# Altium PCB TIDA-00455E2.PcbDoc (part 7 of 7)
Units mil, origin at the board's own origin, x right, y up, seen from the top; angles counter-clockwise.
Board outline 6693 x 6693.1 mil, 8 copper layers (Layer 1 - Top Layer, Layer 2 - GND, Layer 3 - Sensitive, Layer 4 - GND, Layer 5 - PWR, Layer 6 - Signal, Layer 7 - GND, Layer 8 - Bottom Layer), stack 63.122 mil thick; 537 components, 407 nets, 1686 pads, 1249 vias.
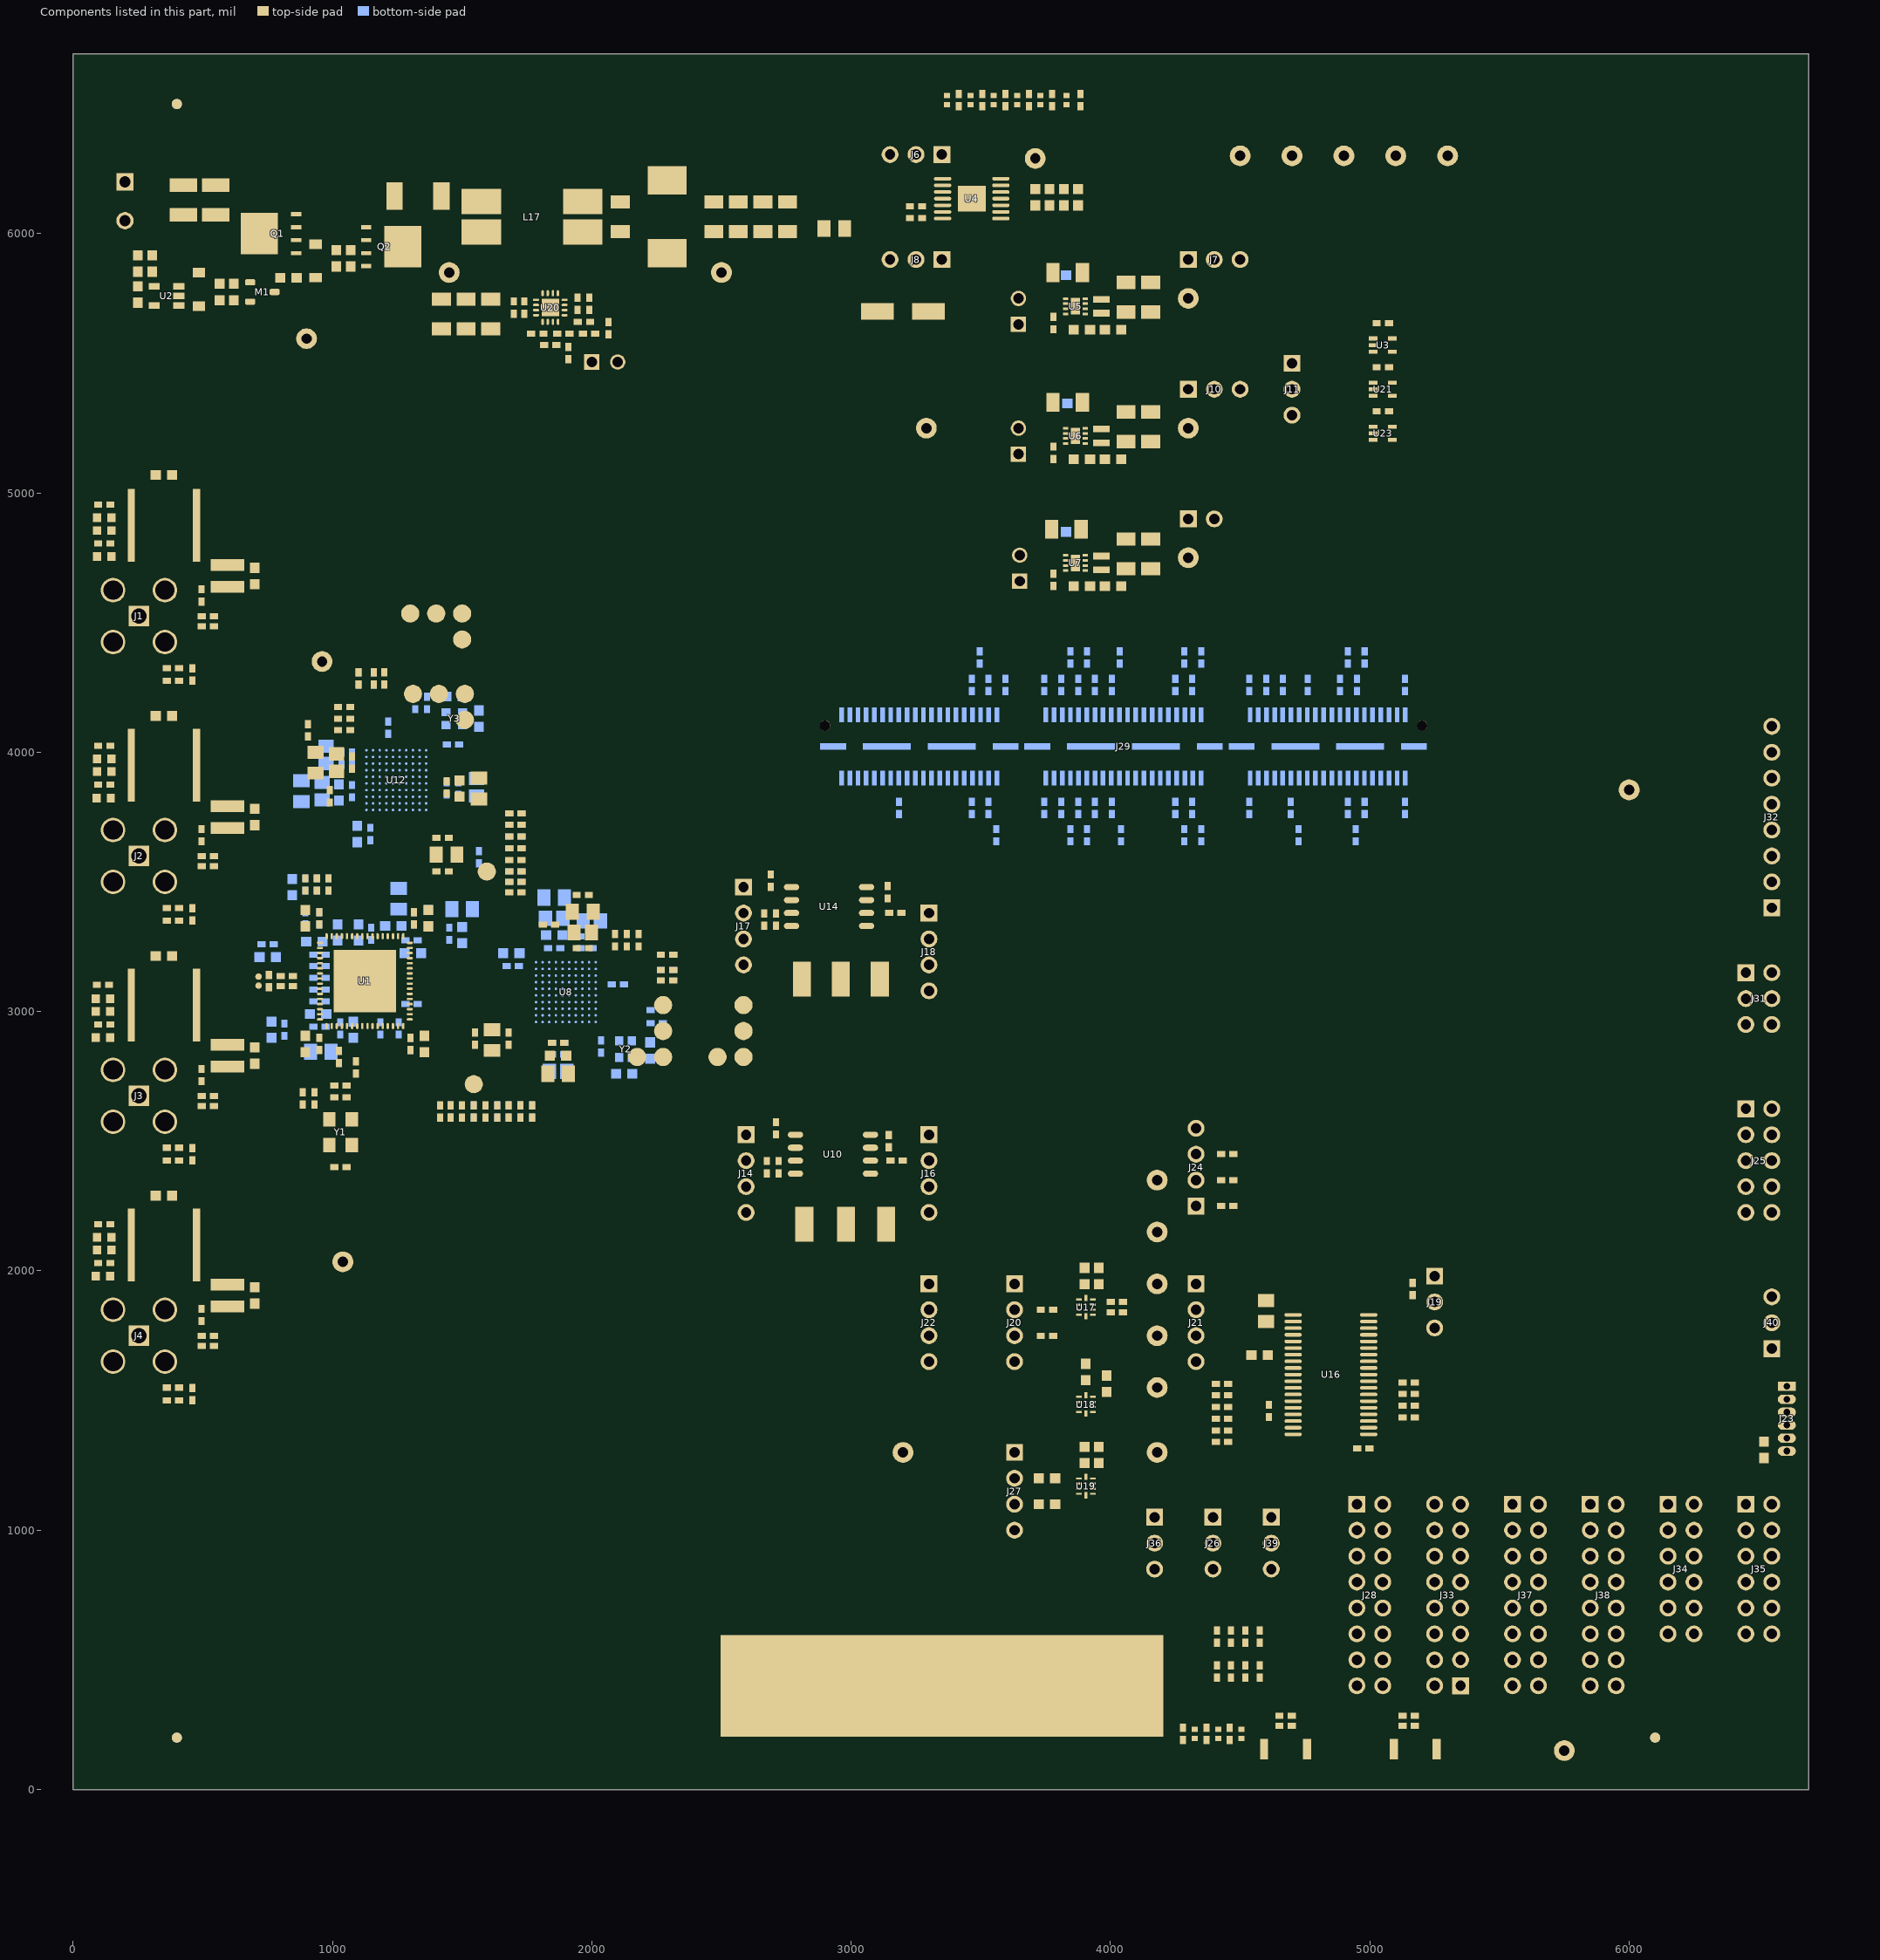
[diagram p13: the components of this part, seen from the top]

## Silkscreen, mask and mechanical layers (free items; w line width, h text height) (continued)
M12 Stackup:
  drawing of 503 lines, arcs and shapes, not listed
  text "Layer" at 10520,7853 h45
  text "Name" at 10832.43,7853 h45
  text "Material" at 11894.63,7853 h45
  text "Thickness" at 12544.45,7853 h45
  text "Constant" at 13036.83,7853 h45
  text "Board Layer Stack" at 13469.23,7853 h45
  text "1" at 10520,7763 h45
  text "Top Overlay" at 10832.43,7763 h45
  text "2" at 10520,7673 h45
  text "Top Solder" at 10832.43,7673 h45
  text "Solder Resist" at 11894.63,7673 h45
  text "0.40mil" at 12544.45,7673 h45
  text "3.5" at 13036.83,7673 h45
  text "3" at 10520,7583 h45
  text "Layer 1 - Top Layer" at 10832.43,7583 h45
  text "Copper" at 11894.63,7583 h45
  text "1.40mil" at 12544.45,7583 h45
  text "4" at 10520,7493 h45
  text "Dielectric 1" at 10832.43,7493 h45
  text "370HR" at 11894.63,7493 h45
  text "5.91mil" at 12544.45,7493 h45
  text "4.2" at 13036.83,7493 h45
  text "5" at 10520,7403 h45
  text "Layer 2 - GND" at 10832.43,7403 h45
  text "Copper" at 11894.63,7403 h45
  text "1.42mil" at 12544.45,7403 h45
  text "6" at 10520,7313 h45
  text "Dielectric 2" at 10832.43,7313 h45
  text "370HR" at 11894.63,7313 h45
  text "5.00mil" at 12544.45,7313 h45
  text "4.2" at 13036.83,7313 h45
  text "7" at 10520,7223 h45
  text "Layer 3 - Sensitive" at 10832.43,7223 h45
  text "Copper" at 11894.63,7223 h45
  text "1.42mil" at 12544.45,7223 h45
  text "8" at 10520,7133 h45
  text "Dielectric 3" at 10832.43,7133 h45
  text "370HR" at 11894.63,7133 h45
  text "5.00mil" at 12544.45,7133 h45
  text "4.2" at 13036.83,7133 h45
  text "9" at 10520,7043 h45
  text "Layer 4 - GND" at 10832.43,7043 h45
  text "Copper" at 11894.63,7043 h45
  text "1.42mil" at 12544.45,7043 h45
  text "10" at 10520,6953 h45
  text "Dielectric 4" at 10832.43,6953 h45
  text "370HR" at 11894.63,6953 h45
  text "20.00mil" at 12544.45,6953 h45
  text "4.2" at 13036.83,6953 h45
  text "11" at 10520,6863 h45
  text "Layer 5 - PWR" at 10832.43,6863 h45
  text "Copper" at 11894.63,6863 h45
  text "1.42mil" at 12544.45,6863 h45
  text "12" at 10520,6773 h45
  text "Dielectric 5" at 10832.43,6773 h45
  text "370HR" at 11894.63,6773 h45
  text "5.00mil" at 12544.45,6773 h45
  text "4.2" at 13036.83,6773 h45
  text "13" at 10520,6683 h45
  text "Layer 6 - Signal" at 10832.43,6683 h45
  text "Copper" at 11894.63,6683 h45
  text "1.42mil" at 12544.45,6683 h45
  text "14" at 10520,6593 h45
  text "Dielectric 6" at 10832.43,6593 h45
  text "370HR" at 11894.63,6593 h45
  text "5.00mil" at 12544.45,6593 h45
  text "4.2" at 13036.83,6593 h45
  text "15" at 10520,6503 h45
  text "Layer 7 - GND" at 10832.43,6503 h45
  text "Copper" at 11894.63,6503 h45
  text "1.42mil" at 12544.45,6503 h45
  text "16" at 10520,6413 h45
  text "Dielectric 7" at 10832.43,6413 h45
  text "370HR" at 11894.63,6413 h45
  text "5.91mil" at 12544.45,6413 h45
  text "4.2" at 13036.83,6413 h45
  text "17" at 10520,6323 h45
  text "Layer 8 - Bottom Layer" at 10832.43,6323 h45
  text "Copper" at 11894.63,6323 h45
  text "1.40mil" at 12544.45,6323 h45
  text "18" at 10520,6233 h45
  text "Bottom Solder" at 10832.43,6233 h45
  text "Solder Resist" at 11894.63,6233 h45
  text "0.40mil" at 12544.45,6233 h45
  text "3.5" at 13036.83,6233 h45
  text "19" at 10520,6143 h45
  text "Bottom Overlay" at 10832.43,6143 h45
  text ".Layer_Name" at 577,-858.49 h60
M13 Component Bodies Top:
  text ".Layer_Name" at 577,-858.49 h60
M14 Component Bodies Bottom:
  text ".Layer_Name" at 577,-858.49 h60
M15 Courtyards Top:
  text ".Layer_Name" at 577,-858.49 h60
M16 Courtyards Bottom:
  text ".Layer_Name" at 577,-858.49 h60
Drill Drawing:
  circle w1: c7236.82,1112.77 r24.92
  circle w1: c7236.82,365.27 r14.95
  circle w1: c7236.82,365.27 r24.92
  lines w1: 7211.91,240.68 7261.74,240.68 7236.82,190.85 7211.91,240.68 ; 7211.91,489.85 7261.74,489.85 7261.74,539.68 7211.91,539.68 7211.91,489.85 ; 7211.91,651.81 7224.37,651.81 7224.37,639.35 7249.28,639.35 7249.28,651.81 7261.74,651.81 7261.74,676.72 7249.28,676.72 7249.28,689.18 7224.37,689.18 7224.37,676.72 7211.91,676.72 7211.91,651.81 ; 7211.91,801.31 7224.37,801.31 7236.82,788.85 7249.28,801.31 7261.74,801.31 7249.28,813.77 7261.74,826.22 7249.28,826.22 7236.82,838.68 7224.37,826.22 7211.91,826.22 7224.37,813.77 7211.91,801.31 ; 7211.91,938.35 7236.82,950.81 7261.74,938.35 7249.28,963.27 7261.74,988.18 7236.82,975.72 7211.91,988.18 7224.37,963.27 7211.91,938.35 ; 7211.91,1262.27 7236.82,1237.35 7261.74,1262.27 7236.82,1287.18 7211.91,1262.27 ; 7211.91,1436.68 7261.74,1436.68 7236.82,1386.85 7211.91,1436.68 ; 7221.88,230.72 7251.77,230.72 7236.82,200.82 7221.88,230.72 ; 7221.88,499.82 7251.77,499.82 7251.77,529.72 7221.88,529.72 7221.88,499.82 ; 7221.88,806.29 7229.35,806.29 7236.82,798.82 7244.3,806.29 7251.77,806.29 7244.3,813.77 7251.77,821.24 7244.3,821.24 7236.82,828.72 7229.35,821.24 7221.88,821.24 7229.35,813.77 7221.88,806.29
  lines w12: 7144,146 9262.44,146 ; 7144,1491.5 9262.44,1491.5 ; 7514.51,-3.5 7514.51,1641 ; 7871.67,-3.5 7871.67,1641 ; 8533.15,-3.5 8533.15,1641 ; 8817.35,-3.5 8817.35,1641 ; 7144,-3.5 9262.44,-3.5 9262.44,1641 7144,1641 7144,-3.5
  text "Symbol" at 7233.7,1536.35 h72
  text "Quantity" at 7559.36,1536.35 h72
  text "Finished Hole Size" at 7916.52,1536.35 h72
  text "Plated" at 8578,1536.35 h72
  text "Hole Type" at 8862.2,1536.35 h72
  text "2" at 7559.36,1386.85 h60
  text "40.16mil (1.020mm)" at 7916.52,1386.85 h60
  text "NPTH" at 8578,1386.85 h60
  text "Round" at 8862.2,1386.85 h60
  text "140" at 7559.36,1237.35 h60
  text "6.00mil (0.152mm)" at 7916.52,1237.35 h60
  text "PTH" at 8578,1237.35 h60
  text "Round" at 8862.2,1237.35 h60
  text "46" at 7559.36,1087.85 h60
  text "7.87mil (0.200mm)" at 7916.52,1087.85 h60
  text "PTH" at 8578,1087.85 h60
  text "Round" at 8862.2,1087.85 h60
  text "1063" at 7559.36,938.35 h60
  text "10.00mil (0.254mm)" at 7916.52,938.35 h60
  text "PTH" at 8578,938.35 h60
  text "Round" at 8862.2,938.35 h60
  text "6" at 7559.36,788.85 h60
  text "26.00mil (0.660mm)" at 7916.52,788.85 h60
  text "PTH" at 8578,788.85 h60
  text "Round" at 8862.2,788.85 h60
  text "212" at 7559.36,639.35 h60
  text "40.00mil (1.016mm)" at 7916.52,639.35 h60
  text "PTH" at 8578,639.35 h60
  text "Round" at 8862.2,639.35 h60
  text "2" at 7559.36,489.85 h60
  text "43.31mil (1.100mm)" at 7916.52,489.85 h60
  text "PTH" at 8578,489.85 h60
  text "Round" at 8862.2,489.85 h60
  text "4" at 7559.36,340.35 h60
  text "59.06mil (1.500mm)" at 7916.52,340.35 h60
  text "PTH" at 8578,340.35 h60
  text "Round" at 8862.2,340.35 h60
  text "16" at 7559.36,190.85 h60
  text "74.80mil (1.900mm)" at 7916.52,190.85 h60
  text "PTH" at 8578,190.85 h60
  text "Round" at 8862.2,190.85 h60
  text "1491 Total" at 7559.36,41.35 h60
  text ".Layer_Name" at 577,-858.49 h60
Mechanical 31:
  lines w0.5: 0,6693.1 6693,6693.1 ; 1713.5,6687.6 1714,6688.1 2255.5,6688.1 ; 4718.5,6692.6 4719,6693.1 5260.5,6693.1 ; 5778,6693.1 6388,6693.1
  lines w1: 0,6693.1 0,0 6693,0 6693,6693.1
Mechanical 32:
  drawing of 19798 lines, arcs and shapes, not listed
  text "1" at -671.51,3744.97 h20 r90
  text "A9" at 2986,703.1 h8
  text "A1" at 3436,703.1 h8
  text "A9" at 3551,703.1 h8
  text "A1" at 4001,703.1 h8
  text "+" at 6583,703.1 h40 r90
  text "+" at 6298,423.1 h40 r90
  text "N6" at 2991,323.1 h8
  text "N1" at 3436,323.1 h8
  text "N6" at 3556,323.1 h8
  text "N1" at 4001,323.1 h8

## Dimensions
0,0 to 6693,0 on M2 Board Dimensions
0,0 to 0,6693.1 on M2 Board Dimensions
0,-400 to 1000,-400 on M2 Board Dimensions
